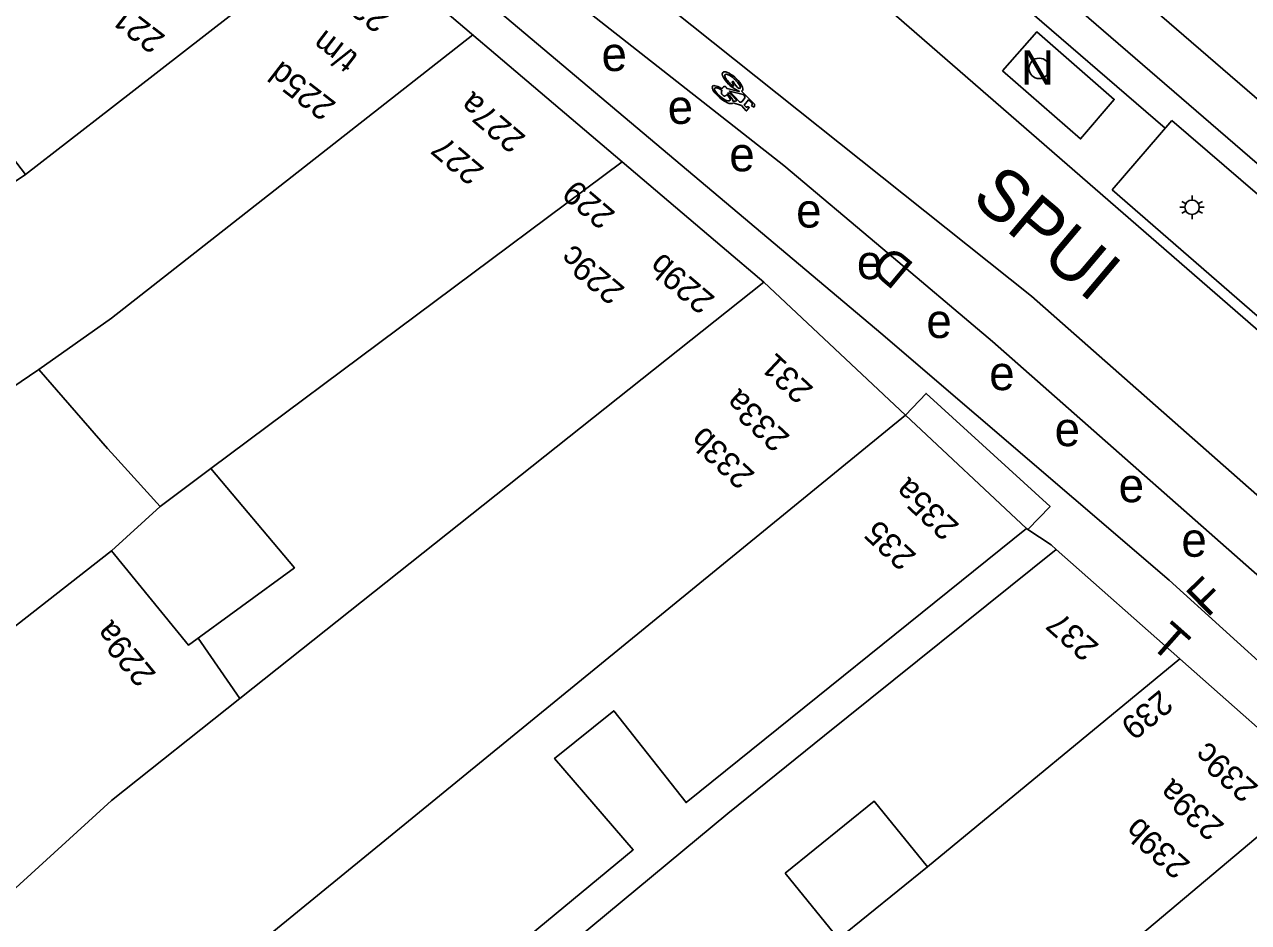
# Model space of a CAD drawing. Extents: x 81617 to 82144, y 454649 to 455150.
# Drawn here: x 81697.46 to 81733.29, y 454680 to 454706.31 of the extents above; entities that cross this region are included whole.
import ezdxf

# ---------------------------------------------------------------- set-up
doc = ezdxf.new("R2010")
doc.units = 0
doc.layers.add('B-WE-OG-TOPOGRAFIE-G', color=7, linetype='Continuous')
doc.layers.add('B-WE-VW-MARKERING-G', color=7, linetype='Continuous')

msp = doc.modelspace()

# ---------------------------------------------------------------- linework, layer by layer
at = {"layer": 'B-WE-OG-TOPOGRAFIE-G'}
for p, q in [((81703.871, 454726.575), (81730.855, 454703.267)), ((81700, 454703.869), (81706.847, 454709.185)), ((81709.216, 454708.492), (81722.53, 454697.265)), ((81700, 454697.709), (81710.585, 454706.004)), ((81697.487, 454701.918), (81700, 454703.869)), ((81731.051, 454703.494), (81729.3, 454701.466)), ((81731.051, 454703.494), (81735.213, 454699.899)), ((81702.916, 454693.301), (81714.953, 454702.287)), ((81731.638, 454701.152), (81731.638, 454701.302)), ((81731.427, 454700.952), (81731.285, 454700.952)), ((81731.465, 454701.052), (81731.335, 454701.127)), ((81731.465, 454700.852), (81731.335, 454700.777)), ((81731.811, 454701.052), (81731.941, 454701.127)), ((81731.811, 454700.852), (81731.941, 454700.777)), ((81731.992, 454700.952), (81731.85, 454700.952)), ((81731.638, 454700.752), (81731.638, 454700.602)), ((81703.761, 454686.565), (81719.1, 454698.758)), ((81697.881, 454696.204), (81700, 454697.709)), ((81722.53, 454697.265), (81730.968, 454690.035)), ((81700.206, 454676.039), (81723.254, 454694.862)), ((81723.254, 454694.862), (81726.796, 454691.541)), ((81701.424, 454692.188), (81700, 454690.889)), ((81726.829, 454691.519), (81726.796, 454691.541)), ((81726.829, 454691.519), (81727.515, 454691.063)), ((81727.515, 454691.063), (81727.664, 454690.931)), ((81730.968, 454690.035), (81736.067, 454685.401)), ((81702.542, 454688.331), (81703.761, 454686.565)), ((81723.893, 454681.633), (81731.283, 454687.723)), ((81700, 454683.576), (81703.761, 454686.565)), ((81696.461, 454680.345), (81700, 454683.576))]:
    msp.add_line(p, q, dxfattribs=at)
for points in [[(81711.061, 454723.559), (81760.224, 454681.093)], [(81710.123, 454722.473), (81759.251, 454680.037)], [(81704.937, 454722.283), (81708.662, 454719.021), (81727.987, 454702.211)], [(81695.133, 454721.257), (81710.923, 454709.073), (81719.683, 454702.175)], [(81700, 454714.463), (81706.847, 454709.185), (81714.953, 454702.287), (81717.886, 454699.79), (81719.1, 454698.758), (81723.254, 454694.862)], [(81700, 454693.76), (81699.888, 454693.884), (81697.881, 454696.204), (81697.087, 454695.661), (81694.275, 454693.457), (81691.968, 454696.655), (81693.864, 454698.013), (81693.12, 454698.851), (81694.811, 454700.118), (81697.487, 454701.918), (81694.423, 454705.904), (81692.598, 454704.296), (81687.809, 454710.22), (81687.395, 454709.889), (81684.558, 454707.482), (81681.659, 454710.717)], [(81726.091, 454704.947), (81727.094, 454706.091), (81729.359, 454704.113), (81728.374, 454702.956), (81726.091, 454704.947)], [(81722.581, 454699.735), (81719.683, 454702.175)], [(81727.987, 454702.211), (81739.09, 454692.554), (81752.463, 454680.921), (81755.021, 454678.695)], [(81729.3, 454701.466), (81739.287, 454692.78), (81752.66, 454681.147), (81755.218, 454678.921)], [(81753.001, 454673.256), (81749.115, 454676.722), (81735.271, 454688.668), (81725.797, 454697.026), (81722.581, 454699.735)], [(81723.254, 454694.862), (81723.851, 454695.5), (81727.48, 454692.194), (81726.829, 454691.519)], [(81700, 454690.889), (81702.262, 454688.126), (81705.358, 454690.394), (81702.916, 454693.301), (81701.424, 454692.188), (81700, 454693.76)], [(81726.796, 454691.541), (81716.827, 454683.516), (81714.706, 454686.208), (81712.975, 454684.809), (81715.281, 454682.136), (81709.19, 454677.095), (81708.906, 454677.365), (81703.572, 454673.043)], [(81690.86, 454675.862), (81693.167, 454677.748), (81693.226, 454677.694), (81696.461, 454680.345), (81695.069, 454682.109), (81693.441, 454680.727), (81690.98, 454683.836), (81700, 454690.889)], [(81712.245, 454665.322), (81716.192, 454668.239), (81709.857, 454675.928), (81709.624, 454676.21), (81718.047, 454683.199), (81720.875, 454685.478), (81727.664, 454690.931)], [(81727.664, 454690.931), (81731.283, 454687.723), (81735.406, 454684.071), (81740.258, 454679.771), (81745.134, 454675.451), (81731.189, 454665.536), (81728.959, 454663.85), (81725.968, 454661.587)], [(81721.377, 454672.411), (81725.093, 454675.401), (81735.406, 454684.071)], [(81719.728, 454681.448), (81722.335, 454683.558), (81723.893, 454681.633), (81721.286, 454679.522), (81719.728, 454681.448)]]:
    msp.add_lwpolyline(points, dxfattribs=at)
for centre, radius in [((81727.163, 454705.021), 0.3), ((81731.638, 454700.952), 0.212)]:
    msp.add_circle(centre, radius, dxfattribs=at)
at = {"layer": 'B-WE-VW-MARKERING-G'}
for points in [[(81754.205, 454674.562), (81750.269, 454678.038), (81736.422, 454689.987), (81726.94, 454698.352), (81714.491, 454708.275)], [(81717.862, 454704.388), (81717.861, 454704.388)], [(81718.371, 454704.348), (81718.029, 454704.431)], [(81718.494, 454704.26), (81718.096, 454704.357), (81718.387, 454704.041)], [(81718.31, 454704.08), (81718.133, 454704.271)], [(81718.452, 454704.357), (81718.819, 454703.985)], [(81718.463, 454704.055), (81718.546, 454704.16)], [(81718.756, 454703.995), (81718.65, 454704.1), (81718.526, 454703.945), (81718.59, 454703.875)], [(81718.45, 454703.939), (81718.2, 454704.015)], [(81718.583, 454703.782), (81718.45, 454703.939)], [(81718.795, 454703.894), (81718.738, 454703.929)]]:
    msp.add_lwpolyline(points, dxfattribs=at)
for centre, major_axis, ratio, start_param, end_param in [((81718.186, 454704.638), (-0.286, 0.267), 0.347295, 2.96728, 8.866181), ((81718.185, 454704.637), (0.216, -0.203), 0.314923, 6.119765, 11.366748), ((81717.896, 454704.252), (-0.297, 0.247), 0.321424, 5.05591, 9.527032), ((81717.886, 454704.26), (-0.226, 0.183), 0.307671, 5.036104, 10.606899), ((81718.196, 454704.623), (0.016, -0.0128), 0.980296, 0.933004, 4.202582), ((81717.924, 454704.481), (0.228, -0.181), 0.980296, 0.769914, 1.166655), ((81718.206, 454704.505), (0.00474, -0.00378), 0.980296, 5.132399, 7.244068), ((81718.695, 454704.849), (0.419, -0.334), 0.980296, 4.25523, 4.724374), ((81718.392, 454704.451), (0.0208, -0.0166), 0.980296, 4.515962, 5.19261), ((81717.886, 454704.26), (-0.226, 0.183), 0.307671, 4.323714, 4.330532), ((81717.896, 454704.252), (-0.297, 0.247), 0.321424, 4.483593, 4.485729), ((81717.896, 454704.252), (-0.297, 0.247), 0.321424, 3.553903, 4.483593), ((81718.417, 454704.096), (0.0483, -0.0385), 0.980296, 4.868752, 6.235806), ((81718.468, 454704.182), (0.0649, -0.0517), 0.980296, 0.416101, 1.916869), ((81718.692, 454703.979), (0.0531, -0.0423), 0.980296, 6.106821, 7.217969)]:
    msp.add_ellipse(centre, major_axis=major_axis, ratio=ratio, start_param=start_param, end_param=end_param, dxfattribs=at)
for points in [[(81718.029, 454704.431), (81718.023, 454704.435), (81718.016, 454704.441), (81718.009, 454704.449), (81718.007, 454704.457), (81717.999, 454704.47), (81717.99, 454704.48), (81717.979, 454704.487), (81717.966, 454704.494), (81717.949, 454704.494), (81717.939, 454704.492), (81717.913, 454704.472), (81717.9, 454704.458), (81717.869, 454704.427)], [(81718.024, 454704.256), (81718.012, 454704.244), (81717.997, 454704.23), (81717.978, 454704.218), (81717.968, 454704.213), (81717.958, 454704.211), (81717.945, 454704.212), (81717.927, 454704.219), (81717.89, 454704.247), (81717.879, 454704.26), (81717.863, 454704.282), (81717.858, 454704.3), (81717.86, 454704.315), (81717.867, 454704.348), (81717.869, 454704.384)], [(81718.133, 454704.271), (81718.111, 454704.288), (81718.093, 454704.298), (81718.073, 454704.298), (81718.041, 454704.288)], [(81718.198, 454704.063), (81718.255, 454704.061), (81718.283, 454704.067), (81718.31, 454704.08)], [(81718.381, 454704.359), (81718.385, 454704.353), (81718.383, 454704.348), (81718.371, 454704.348)], [(81718.669, 454703.886), (81718.67, 454703.882), (81718.67, 454703.88), (81718.67, 454703.877), (81718.667, 454703.874), (81718.658, 454703.86), (81718.636, 454703.83), (81718.622, 454703.811), (81718.61, 454703.796), (81718.605, 454703.79), (81718.601, 454703.781), (81718.596, 454703.777), (81718.594, 454703.776), (81718.592, 454703.775), (81718.59, 454703.775), (81718.588, 454703.776), (81718.584, 454703.78), (81718.583, 454703.782), (81718.581, 454703.784)], [(81718.59, 454703.875), (81718.6, 454703.887), (81718.618, 454703.899), (81718.637, 454703.899), (81718.655, 454703.894), (81718.669, 454703.886)], [(81718.819, 454703.985), (81718.83, 454703.956), (81718.832, 454703.938), (81718.825, 454703.91), (81718.803, 454703.89), (81718.795, 454703.894)]]:
    msp.add_spline(points, degree=3, dxfattribs=at)

# ---------------------------------------------------------------- texts
at = {"layer": 'B-WE-OG-TOPOGRAFIE-G'}
for s, height, rotation, p in [('225', 0.7, 142.3587, (81708.196, 454706.566)), ('221d', 0.7, 142.3587, (81701.614, 454705.96)), ('t/m', 0.7, 142.3587, (81707.266, 454705.389)), ('e', 1, 1.9612, (81714.364, 454704.931)), ('225d', 0.7, 142.3587, (81706.614, 454703.998)), ('227a', 0.7, 139.6081, (81712.165, 454703.02)), ('e', 1, 1.9612, (81716.302, 454703.383)), ('227', 0.7, 139.6081, (81710.952, 454702.082)), ('SPUI', 1.5, 319.83, (81725.132, 454701.155)), ('229', 0.7, 139.598, (81714.788, 454700.787)), ('229c', 0.7, 139.603, (81715.069, 454698.578)), ('229b', 0.7, 139.598, (81717.706, 454698.304)), ('D', 1, 140.0693, (81723.541, 454699.271)), ('231', 0.7, 136.8397, (81720.584, 454695.653)), ('233a', 0.7, 136.8397, (81719.898, 454694.241)), ('233b', 0.7, 136.8397, (81718.872, 454693.147)), ('235a', 0.7, 136.8397, (81724.856, 454691.648)), ('235', 0.7, 136.8397, (81723.599, 454690.77)), ('F', 1, 44.5953, (81732.091, 454688.914)), ('237', 0.7, 138.4562, (81728.946, 454688.126)), ('229a', 0.7, 129.5208, (81701.335, 454687.287)), ('T', 1, 318.4166, (81730.369, 454688.126)), ('239', 0.7, 219.4923, (81730.705, 454686.844)), ('239c', 0.7, 138.4562, (81733.615, 454683.989)), ('239a', 0.7, 138.4562, (81732.619, 454682.867)), ('239b', 0.7, 138.4562, (81731.624, 454681.745))]:
    msp.add_text(s, height=height, rotation=rotation, dxfattribs=at).set_placement(p)
for s, p in [('N', (81726.631, 454704.547)), ('e', (81718.09, 454702.007)), ('e', (81720.048, 454700.36)), ('e', (81721.826, 454698.848)), ('e', (81723.861, 454697.124)), ('e', (81725.7, 454695.598)), ('e', (81727.615, 454693.957)), ('e', (81729.489, 454692.315)), ('e', (81731.327, 454690.718))]:
    msp.add_text(s, height=1, dxfattribs=at).set_placement(p)

doc.saveas('drawing.dxf')
